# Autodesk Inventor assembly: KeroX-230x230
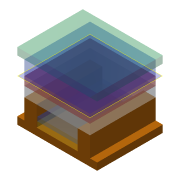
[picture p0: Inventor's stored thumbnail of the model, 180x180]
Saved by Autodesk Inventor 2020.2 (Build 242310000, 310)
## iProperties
Created: 2015-11
Part Number: KeroX-230x230
Document SubType Name: Assembly
Designer: F.Stasiak
Catalog Web Link: www.expertbooks.pl
Manager: www.cadconsulting.pl
Company: Fabian Stasiak CAD Consulting
Author: F.Stasiak
Subject: Zbiór ćwiczeń. Autodesk Inventor 2020. Kurs Professional
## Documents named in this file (9)
- C:\2020_Kurs_Professional\R6 Formy\Redagowanie\100_KeroX-230x230.iam
- C:\2020_Kurs_Professional\R6 Formy\Redagowanie\DPZ-230x280x25.ipt
- C:\2020_Kurs_Professional\R6 Formy\Redagowanie\PW-230x140x20.ipt
- C:\2020_Kurs_Professional\R6 Formy\Redagowanie\PPW-230x140x15.ipt
- C:\2020_Kurs_Professional\R6 Formy\Redagowanie\BD-230x43x70.ipt
- C:\2020_Kurs_Professional\R6 Formy\Redagowanie\PP-230x230x35.ipt
- C:\2020_Kurs_Professional\R6 Formy\Redagowanie\PS-230x230x30.ipt
- C:\2020_Kurs_Professional\R6 Formy\Redagowanie\PM-230x230x50.ipt
- C:\2020_Kurs_Professional\R6 Formy\Redagowanie\GPZ-230x280x25.ipt
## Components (9 placed, 8 different names)
1. DPZ-230x280x25:1 — Równoległy:1, Równoległy:3, Równoległy:4, Zestawiający:2, Równoległy:6
2. PW-230x140x20:1 — Równoległy:1, Równoległy:2, Zestawiający:1, Zestawiający:3
3. PPW-230x140x15:1 — Równoległy:2
4. BD-230x43x70:1 — Równoległy:3, Równoległy:4, Zestawiający:1, Równoległy:5
5. BD-230x43x70:2 — Zestawiający:2, Równoległy:5, Zestawiający:3, Zestawiający:4, Równoległy:7
6. PP-230x230x35:1 — Zestawiający:4, Równoległy:6, Równoległy:7, Równoległy:8
7. PS-230x230x30:1 — Równoległy:8, Równoległy:9, Zestawiający:12
8. PM-230x230x50:1 — Równoległy:9, Równoległy:10
9. GPZ-230x280x25:1 — Równoległy:10
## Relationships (15: Flush 10, Mate 5)
- Równoległy:1 [Flush]: DPZ-230x280x25:1 ↔ PW-230x140x20:1
- Równoległy:2 [Flush]: PW-230x140x20:1 ↔ PPW-230x140x15:1
- Równoległy:3 [Flush]: DPZ-230x280x25:1 ↔ BD-230x43x70:1
- Równoległy:4 [Flush]: DPZ-230x280x25:1 ↔ BD-230x43x70:1
- Zestawiający:1 [Mate]: PW-230x140x20:1 ↔ BD-230x43x70:1
- Zestawiający:2 [Mate]: DPZ-230x280x25:1 ↔ BD-230x43x70:2
- Równoległy:5 [Flush]: BD-230x43x70:1 ↔ BD-230x43x70:2
- Zestawiający:3 [Mate]: PW-230x140x20:1 ↔ BD-230x43x70:2
- Zestawiający:4 [Mate]: BD-230x43x70:2 ↔ PP-230x230x35:1
- Równoległy:6 [Flush]: DPZ-230x280x25:1 ↔ PP-230x230x35:1
- Równoległy:7 [Flush]: BD-230x43x70:2 ↔ PP-230x230x35:1
- Równoległy:8 [Flush]: PP-230x230x35:1 ↔ PS-230x230x30:1
- Równoległy:9 [Flush]: PS-230x230x30:1 ↔ PM-230x230x50:1
- Równoległy:10 [Flush]: PM-230x230x50:1 ↔ GPZ-230x280x25:1
- Zestawiający:12 [Mate]: PS-230x230x30:1
